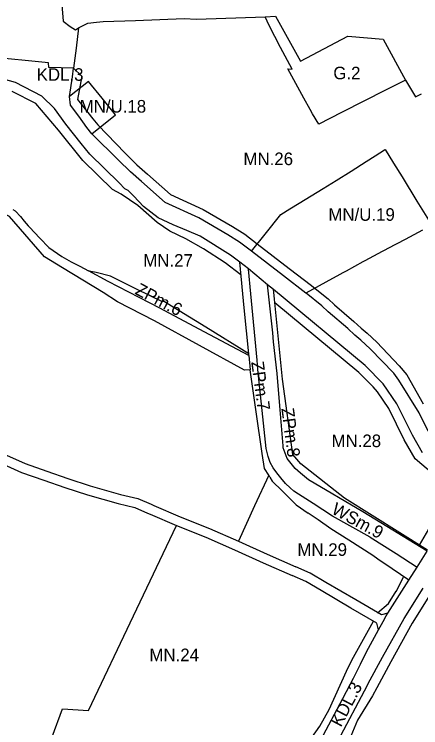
# Model space of a CAD drawing. Extents: x 7431080 to 7433370, y 5546450 to 5548428.
# Drawn here: x 7432304.1 to 7432562.3, y 5547510.7 to 5547964 of the extents above; entities that cross this region are included whole.
import ezdxf

# ---------------------------------------------------------------- set-up
doc = ezdxf.new("R2010")
doc.units = 0
for name, color, linetype in [('Linie Rozgraniczajace', 7, 'Continuous'), ('nieprzekraczalna linia zabudowy', 7, 'Continuous'), ('oznaczenia_przeznaczen', 7, 'Continuous')]:
    doc.layers.add(name, color=color, linetype=linetype)

msp = doc.modelspace()

# ---------------------------------------------------------------- linework, layer by layer
at = {"layer": 'Linie Rozgraniczajace'}
for p, q in [((7432351.27, 5547921.16), (7432339.06, 5547911.63)), ((7432359.81, 5547910.64), (7432351.27, 5547921.16)), ((7432339.88, 5547906.18), (7432339.06, 5547911.63)), ((7432368.35, 5547900.13), (7432359.81, 5547910.64)), ((7432344.99, 5547899.13), (7432339.88, 5547906.18)), ((7432350.1, 5547892.09), (7432344.99, 5547899.13)), ((7432353.31, 5547887.9), (7432368.35, 5547900.13)), ((7432353.31, 5547887.9), (7432350.1, 5547892.09)), ((7432370.3, 5547871.33), (7432353.31, 5547887.9)), ((7432453.09, 5547748.25), (7432450.16, 5547777.37)), ((7432484.57, 5547659.08), (7432481.63, 5547660.92)), ((7432491.97, 5547608.85), (7432482.96, 5547612.86)), ((7432489.23, 5547603.51), (7432480.52, 5547607.38)), ((7432501.99, 5547603), (7432491.97, 5547608.85)), ((7432498.95, 5547597.82), (7432489.23, 5547603.51)), ((7432520.97, 5547591.88), (7432501.99, 5547603)), ((7432517.93, 5547586.7), (7432498.95, 5547597.82))]:
    msp.add_line(p, q, dxfattribs=at)
for points in [[(7432339.06, 5547911.63), (7432340.97, 5547924.32), (7432341.7, 5547929.78), (7432325.96, 5547930.12), (7432325.9, 5547933.15), (7432287.28, 5547936.86), (7432271.08, 5547939.75), (7432250.79, 5547940.49), (7432209.67, 5547944.14), (7432182.62, 5547946.34), (7432167.68, 5547951.47), (7432162.36, 5547958.11), (7432154.41, 5547972.74), (7432154.32, 5547972.91), (7432151.45, 5547978.19)], [(7432333.76, 5547975.57), (7432335.23, 5547959.54), (7432339.64, 5547956.29), (7432342.97, 5547954.16), (7432344.94, 5547955.25), (7432350.86, 5547958.24), (7432356.29, 5547959), (7432360.54, 5547959.47), (7432381.17, 5547959.91), (7432412.06, 5547961.21), (7432419.73, 5547960.86), (7432463.49, 5547962.32), (7432470.02, 5547962.81), (7432485.9, 5547934.14), (7432515.92, 5547950.13), (7432538.37, 5547948.06), (7432552.53, 5547922.12), (7432558.92, 5547911.54), (7432562.86, 5547913.51)], [(7432552.53, 5547922.12), (7432539.52, 5547915.5), (7432526.5, 5547908.87), (7432512, 5547901.46), (7432497.5, 5547894.05), (7432493.55, 5547900.74), (7432492.08, 5547903.36), (7432488.03, 5547910.56), (7432482.96, 5547919.96), (7432477.88, 5547929.36), (7432480.55, 5547929.08), (7432473.28, 5547942.95), (7432466.01, 5547956.82), (7432463.49, 5547962.32)], [(7432344.94, 5547955.25), (7432343.4, 5547942.42), (7432341.7, 5547929.78)], [(7432321.65, 5547911.99), (7432304.85, 5547920.53), (7432281.67, 5547926.87), (7432264.9, 5547931.36), (7432190.51, 5547937.49), (7432176.95, 5547939.61), (7432169.32, 5547940.25), (7432166.81, 5547940.45), (7432161.29, 5547940.88), (7432150.9, 5547941.84), (7432142.19, 5547935.29)], [(7432352.15, 5547875.15), (7432346.56, 5547881.91), (7432336.84, 5547894.22), (7432329.52, 5547904.08), (7432321.65, 5547911.99)], [(7432454.78, 5547813.38), (7432463.5, 5547824.3), (7432473.36, 5547836.66), (7432479.19, 5547840.25), (7432485.01, 5547843.85), (7432492.69, 5547848.58), (7432500.36, 5547853.32), (7432508.54, 5547858.37), (7432518.03, 5547864.37), (7432527.52, 5547870.37), (7432533.37, 5547874.07), (7432539.21, 5547877.76), (7432539.48, 5547877.92), (7432539.74, 5547878.08), (7432545.07, 5547869.4), (7432550.39, 5547860.71), (7432559.83, 5547845.32), (7432569.26, 5547829.92)], [(7432563.38, 5547685.29), (7432557.16, 5547696.48), (7432547.16, 5547716.55), (7432538.5, 5547729.14), (7432527.07, 5547740.78), (7432468.74, 5547789.08), (7432465.04, 5547792.14), (7432452.88, 5547802.21), (7432447.26, 5547806.55), (7432441.48, 5547811.02), (7432422.26, 5547823.06), (7432413.65, 5547826.66), (7432405.04, 5547830.26), (7432395.54, 5547834.58), (7432386.08, 5547841.9), (7432380.03, 5547848.5), (7432376.32, 5547852.08), (7432374.37, 5547853.09), (7432370.72, 5547856.91), (7432352.15, 5547875.15)], [(7432587.74, 5547679.83), (7432579.8, 5547684.51), (7432571.24, 5547691.74), (7432566.01, 5547701.14), (7432561.27, 5547710.64), (7432548.45, 5547731.47), (7432545.14, 5547735.9), (7432530.25, 5547751.38), (7432524.17, 5547756.85), (7432520.51, 5547760.07), (7432515.88, 5547764.35), (7432503.45, 5547774.93), (7432499.46, 5547778.72), (7432489.5, 5547786.69), (7432489.3, 5547786.84), (7432475.05, 5547797.72), (7432454.78, 5547813.38), (7432447.21, 5547819.23), (7432439.7, 5547823.93), (7432421.26, 5547834.62), (7432399.96, 5547844.46), (7432384.82, 5547857.78), (7432377.84, 5547863.93), (7432370.3, 5547871.33)], [(7432453.95, 5547738.05), (7432450.28, 5547737.86), (7432421.71, 5547753.53), (7432393.13, 5547769.16), (7432369.7, 5547781.35), (7432360.44, 5547787.23), (7432334.74, 5547802.88), (7432323.37, 5547809.83), (7432301.06, 5547835.46), (7432294.22, 5547838.83), (7432284.43, 5547842.82), (7432283.6, 5547843.16), (7432252.46, 5547855.2), (7432245.21, 5547855.78), (7432236.24, 5547856.46), (7432221.24, 5547854.22)], [(7432304.8, 5547838.84), (7432303.34, 5547839.8)], [(7432304.8, 5547838.84), (7432307.92, 5547835.4), (7432310.45, 5547832.48), (7432312.98, 5547829.55), (7432313.81, 5547828.67), (7432320.29, 5547821.76), (7432325.93, 5547815.74), (7432334.38, 5547810.12), (7432340.31, 5547806.72), (7432345.73, 5547803.83), (7432351.14, 5547800.96)], [(7432563.49, 5547826.76), (7432552.4, 5547820.92), (7432541.31, 5547815.07), (7432539.53, 5547814.11), (7432537.74, 5547813.15), (7432532.28, 5547810.23), (7432526.82, 5547807.3), (7432525.55, 5547806.61), (7432520.2, 5547803.69), (7432514.84, 5547800.77), (7432512.88, 5547799.7), (7432510.92, 5547798.63), (7432501.9, 5547793.71), (7432489.3, 5547786.84)], [(7432450.16, 5547777.37), (7432447.26, 5547806.55)], [(7432453.02, 5547747.17), (7432453.09, 5547748.25), (7432425.79, 5547765.08), (7432398.5, 5547781.92), (7432398.26, 5547781.31), (7432381.77, 5547789.41), (7432365.28, 5547797.51), (7432356, 5547799.82), (7432352.74, 5547800.63), (7432351.14, 5547800.96)], [(7432396.55, 5547777.15), (7432363.77, 5547794.29), (7432351.14, 5547800.96)], [(7432481.63, 5547660.92), (7432479.28, 5547663.04), (7432476.44, 5547665.88), (7432473.38, 5547669.38), (7432470.92, 5547672.56), (7432468.46, 5547675.74), (7432466.74, 5547679.19), (7432465.41, 5547683.02), (7432463.99, 5547688.12), (7432458.88, 5547738.31), (7432458.29, 5547744.16), (7432454.41, 5547786.32), (7432452.9, 5547801.98), (7432452.88, 5547802.21)], [(7432472.92, 5547712.69), (7432470.98, 5547735.7), (7432468.8, 5547755.77), (7432468.27, 5547761.51), (7432465.04, 5547792.14)], [(7432566.65, 5547623.4), (7432513.9, 5547656.51), (7432486.02, 5547678.29), (7432481.13, 5547684.37), (7432474.43, 5547732.1), (7432469.33, 5547782.86), (7432468.91, 5547787.5), (7432468.74, 5547789.08)], [(7432453.02, 5547747.17), (7432424.79, 5547762.16), (7432396.55, 5547777.15)], [(7432453.02, 5547747.17), (7432453.95, 5547738.05)], [(7432466.35, 5547669.97), (7432465.7, 5547671.04), (7432463.05, 5547675.39), (7432461.64, 5547684.82), (7432457.79, 5547711.42), (7432453.95, 5547738.05)], [(7432566.3, 5547622.84), (7432525.41, 5547647.78), (7432490.91, 5547668.16), (7432485.92, 5547672.31), (7432482.52, 5547675.32), (7432477.4, 5547681.69), (7432474.91, 5547688.4), (7432474.86, 5547689.68), (7432472.92, 5547712.69)], [(7432285.14, 5547689.9), (7432310.89, 5547678.5), (7432324.8, 5547673.63), (7432338.1, 5547669.08), (7432352.28, 5547664.36), (7432371.54, 5547658.93), (7432382.65, 5547656.27), (7432391.14, 5547652.61), (7432392.71, 5547651.93), (7432409.48, 5547644.73), (7432428.05, 5547637.22), (7432446.52, 5547629.24), (7432464.7, 5547620.99), (7432482.96, 5547612.86)], [(7432282.75, 5547684.39), (7432308.69, 5547672.92), (7432322.84, 5547667.97), (7432336.18, 5547663.4), (7432350.52, 5547658.62), (7432370.02, 5547653.13), (7432380.75, 5547650.55), (7432388.76, 5547647.09), (7432390.35, 5547646.41), (7432407.04, 5547639.25), (7432407.18, 5547639.19), (7432425.73, 5547631.68), (7432444.05, 5547623.78), (7432462.24, 5547615.51), (7432480.52, 5547607.38)], [(7432465.7, 5547671.04), (7432456.76, 5547651.59), (7432446.52, 5547629.24)], [(7432466.35, 5547669.97), (7432467.98, 5547667.39), (7432474.19, 5547661.24), (7432480.39, 5547655.08), (7432483.2, 5547652.29), (7432490.79, 5547647.05)], [(7432530.2, 5547631.8), (7432506.32, 5547645.17), (7432493.91, 5547653.22), (7432484.57, 5547659.08)], [(7432497.08, 5547642.71), (7432490.79, 5547647.05)], [(7432544.16, 5547611.58), (7432535.07, 5547617.78), (7432531.81, 5547620.01), (7432524.21, 5547624.88), (7432516.62, 5547629.76), (7432505.23, 5547637.08), (7432497.08, 5547642.71)], [(7432321.38, 5547487.39), (7432328.05, 5547504.99), (7432334.72, 5547522.59), (7432351.22, 5547521.65), (7432379.78, 5547581.8), (7432407.04, 5547639.25)], [(7432530.2, 5547631.8), (7432546.61, 5547621.29), (7432559.96, 5547612.73)], [(7432440.7, 5547407.28), (7432444.63, 5547410.31), (7432449.78, 5547416.07), (7432455.2, 5547423.95), (7432464.31, 5547439.87), (7432468.3, 5547447.36), (7432482.61, 5547473.81), (7432492.81, 5547492.45), (7432493.84, 5547494.24), (7432498.62, 5547502.57), (7432512.77, 5547529.21), (7432519.57, 5547542.25), (7432520.68, 5547544.37), (7432522.9, 5547548.87), (7432524.02, 5547551.13), (7432527.88, 5547558.92), (7432535.55, 5547572.92), (7432538.43, 5547578.18), (7432540.35, 5547581.69), (7432541.31, 5547583.45), (7432553.31, 5547602.02), (7432554.79, 5547604.33), (7432559.96, 5547612.73), (7432566.3, 5547622.84)], [(7432554.79, 5547604.33), (7432544.16, 5547611.58)], [(7432448.53, 5547398.86), (7432450.95, 5547400.7), (7432452.97, 5547402.89), (7432453.29, 5547403.24), (7432457.88, 5547409.28), (7432463.71, 5547418.69), (7432472.86, 5547434.68), (7432484.51, 5547457.87), (7432486.28, 5547465.16), (7432491.17, 5547474.28), (7432497.66, 5547480.48), (7432502.29, 5547488.87), (7432511.59, 5547505.67), (7432526.59, 5547534.1), (7432528.92, 5547538.55), (7432528.98, 5547538.67), (7432537.97, 5547555.41), (7432551.75, 5547580.08), (7432563.79, 5547599.35)], [(7432541.31, 5547583.45), (7432537.28, 5547582.33), (7432520.97, 5547591.88)], [(7432535.55, 5547572.92), (7432534.4, 5547577.06), (7432517.93, 5547586.7)]]:
    msp.add_lwpolyline(points, dxfattribs=at)
at = {"layer": 'nieprzekraczalna linia zabudowy'}
msp.add_line((7432546.62, 5547597.28), (7432551.36, 5547606.39), dxfattribs=at)
for points in [[(7432341.7, 5547929.78), (7432347.07, 5547924.69), (7432344.29, 5547909.81), (7432346.84, 5547906.62), (7432354.04, 5547897.57), (7432357.17, 5547893.68), (7432374.49, 5547875.63), (7432381.93, 5547868.33), (7432388.78, 5547862.28), (7432403.27, 5547849.54), (7432424.03, 5547839.95), (7432442.8, 5547829.07), (7432450.64, 5547824.16), (7432458.45, 5547818.13), (7432478.7, 5547802.48), (7432492.92, 5547791.62), (7432493.18, 5547791.43), (7432503.41, 5547783.25), (7432507.46, 5547779.39), (7432519.86, 5547768.84), (7432524.53, 5547764.53), (7432528.16, 5547761.33), (7432534.42, 5547755.7), (7432548.69, 5547740.56), (7432553.42, 5547734.84), (7432563.88, 5547716.39)], [(7432448.08, 5547798.32), (7432438.04, 5547806.08), (7432424.36, 5547814.92), (7432413.11, 5547821.25), (7432402.88, 5547826.12), (7432394.94, 5547831.77), (7432394.94, 5547831.77), (7432394.94, 5547831.77), (7432394.94, 5547831.77), (7432382.58, 5547842.49), (7432372, 5547849.77), (7432366.44, 5547852.69), (7432347.68, 5547871.1), (7432332.21, 5547890.38), (7432317.86, 5547907.18), (7432302.67, 5547914.89)], [(7432561.56, 5547626.59), (7432582.2, 5547662.2), (7432581.51, 5547663.56), (7432569.94, 5547671.89), (7432558.68, 5547681.42), (7432551.85, 5547693.68), (7432541.98, 5547713.5), (7432534.91, 5547724.03), (7432532.16, 5547727.33), (7432523.01, 5547736.36), (7432469.56, 5547780.61)], [(7432568.97, 5547596.32), (7432556.92, 5547577.03), (7432543.23, 5547552.53), (7432534.38, 5547536.04), (7432531.68, 5547530.87)], [(7432534.88, 5547583.73), (7432541.78, 5547589.58), (7432546.77, 5547597.53)], [(7432518.58, 5547553.68), (7432532.29, 5547578.3)], [(7432491.98, 5547503.05), (7432498.28, 5547511.7), (7432504.11, 5547522.15), (7432515.11, 5547546.68), (7432518.58, 5547553.68)], [(7432531.68, 5547530.87), (7432522.17, 5547515.54), (7432516.87, 5547502.82), (7432507.54, 5547485.97), (7432502.47, 5547476.78), (7432496.2, 5547472.31), (7432495.04, 5547470.22), (7432495.04, 5547470.22), (7432495.04, 5547470.22), (7432489.83, 5547461.25), (7432472.94, 5547427.95), (7432467.43, 5547417.38), (7432462.83, 5547405.88), (7432456.95, 5547398.15)]]:
    msp.add_lwpolyline(points, dxfattribs=at)

# ---------------------------------------------------------------- texts
at = {"layer": 'oznaczenia_przeznaczen'}
for s, p in [('KDL.3', (7432318.31, 5547921.7)), ('G.2', (7432506.75, 5547922.65)), ('MN/U.18', (7432345.63, 5547901.5)), ('MN.26', (7432449.66, 5547868.12)), ('MN/U.19', (7432503.63, 5547832.75)), ('MN.27', (7432386.02, 5547803.57)), ('MN.28', (7432505.61, 5547688.96)), ('MN.29', (7432483.94, 5547619.86)), ('MN.24', (7432389.92, 5547552.95))]:
    msp.add_text(s, height=8, dxfattribs=at).set_placement(p)
for s, rotation, p in [('ZPm.6', 332.5135, (7432380.18, 5547786.51)), ('ZPm.7', 277.7438, (7432454.56, 5547742.99)), ('ZPm.8', 277.489, (7432473.73, 5547713.41)), ('WSm.9', 331.4299, (7432504.97, 5547647.14)), ('KDL.3', 62.2023, (7432511.54, 5547510.64))]:
    msp.add_text(s, height=8, rotation=rotation, dxfattribs=at).set_placement(p)

doc.saveas('drawing.dxf')
